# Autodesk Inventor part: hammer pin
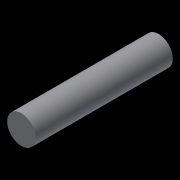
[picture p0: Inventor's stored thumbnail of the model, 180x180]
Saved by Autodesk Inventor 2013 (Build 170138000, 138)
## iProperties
Created: 2013-01
Part Number: hammer pin
Material: Generic
Document SubType Name: Modeling
Designer: John
Density: 1 g/cm^3
Author: John
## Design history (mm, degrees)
sketch "Sketch1"
  geometry: C1 r 2.007 at (0, 0); 1 further point
  constraints: 1 centre point, 1 coincident
  dimensions: "d0" = 4.0132 diameter of C1
extrude "Extrusion1" new body sketch "Sketch1" distance "d1" = 19.3548; taper "d2" = 0 deg
body "Solid1"
